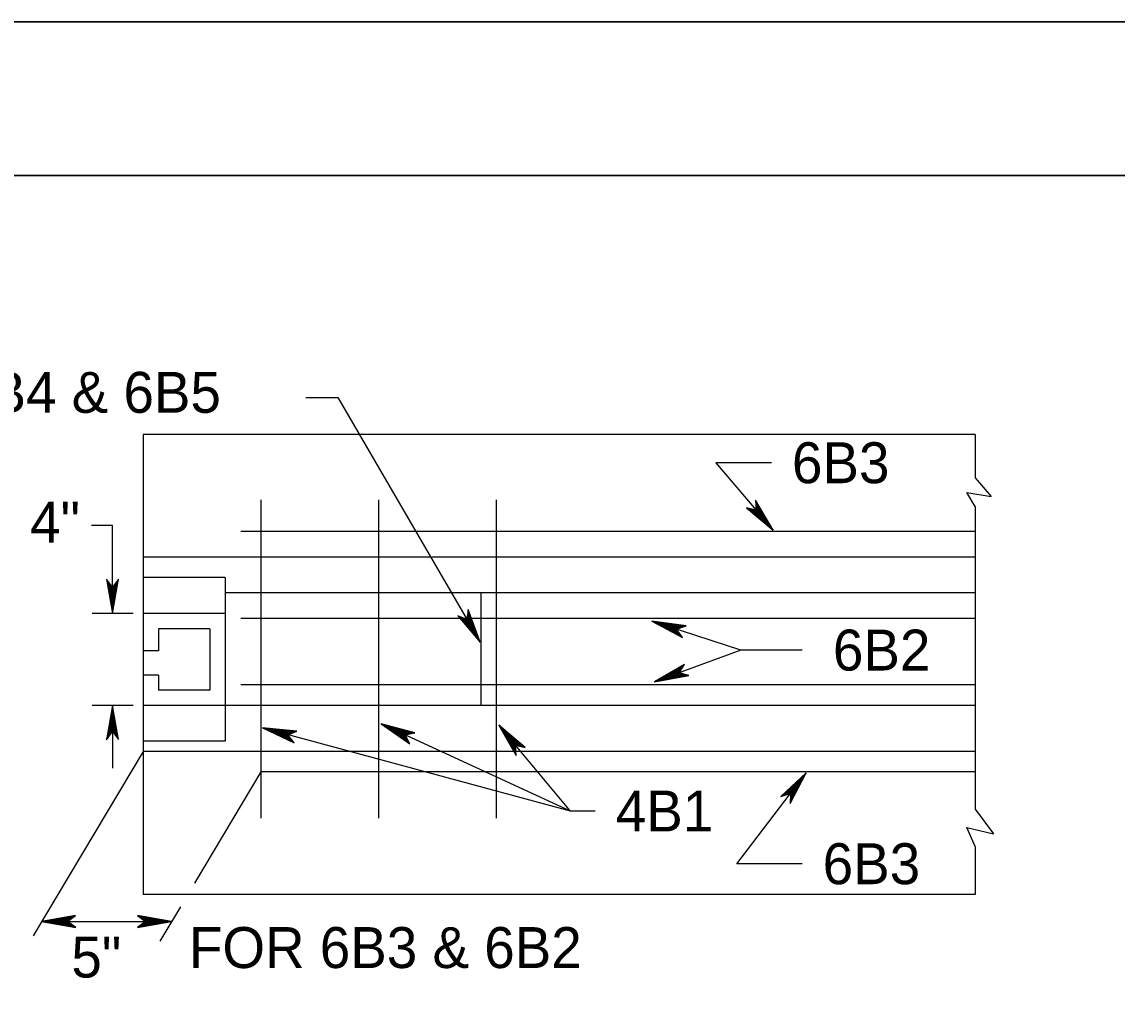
# Model space of a CAD drawing. Extents: x 499883 to 500983, y 499104 to 499764.
# Drawn here: x 500121.3 to 500228.2, y 499669.2 to 499763.6 of the extents above; entities that cross this region are included whole.
import ezdxf

# ---------------------------------------------------------------- set-up
doc = ezdxf.new("R2010")
doc.units = 0
for name, color, linetype in [('1', 7, 'Continuous'), ('24', 7, 'Continuous'), ('41', 7, 'Continuous'), ('5', 7, 'Continuous')]:
    doc.layers.add(name, color=color, linetype=linetype)

msp = doc.modelspace()

# ---------------------------------------------------------------- linework, layer by layer
at = {"layer": '1'}
for p, q in [((500982.94, 499763.64), (499934.77, 499763.64)), ((500979.94, 499748.64), (499989.94, 499748.64))]:
    msp.add_line(p, q, dxfattribs=at)
at = {"layer": '24'}
for points in [[(500194.64, 499714), (500192.91, 499716.93), (500192.98, 499715.94), (500192.03, 499716.16), (500194.64, 499714), (500194.49, 499714.16), (500192.94, 499716.83), (500193.01, 499715.89), (500192.15, 499716.08), (500194.4, 499714.25), (500194.34, 499714.34), (500193, 499716.62), (500193.03, 499715.87), (500192.29, 499716.03), (500194.31, 499714.38), (500194.22, 499714.46), (500193.06, 499716.45), (500193.05, 499715.86), (500192.44, 499715.94), (500194.01, 499714.7), (500193.89, 499714.85), (500193.1, 499716.27), (500193.08, 499715.84), (500192.61, 499715.88), (500193.88, 499714.88), (500193.77, 499715.03), (500193.15, 499716.07), (500193.12, 499715.74), (500192.79, 499715.78), (500193.66, 499715.14), (500193.56, 499715.28), (500193.2, 499715.92), (500193.15, 499715.72), (500192.89, 499715.76), (500193.49, 499715.34), (500193.27, 499715.77), (500193.22, 499715.63), (500192.99, 499715.71), (500193.4, 499715.42), (500193.26, 499715.7), (500193.27, 499715.54), (500193.13, 499715.61), (500193.29, 499715.56), (500193.26, 499715.63)], [(500130.12, 499705.86), (500130.71, 499709.21), (500130.12, 499708.41), (500129.54, 499709.19), (500130.12, 499705.86), (500130.12, 499706.08), (500130.67, 499709.11), (500130.12, 499708.34), (500129.59, 499709.05), (500130.11, 499706.2), (500130.12, 499706.31), (500130.58, 499708.91), (500130.12, 499708.33), (500129.66, 499708.93), (500130.12, 499706.36), (500130.11, 499706.47), (500130.52, 499708.74), (500130.12, 499708.3), (500129.71, 499708.75), (500130.11, 499706.8), (500130.11, 499706.98), (500130.43, 499708.58), (500130.13, 499708.27), (500129.8, 499708.6), (500130.12, 499707.02), (500130.13, 499707.2), (500130.34, 499708.39), (500130.11, 499708.16), (500129.88, 499708.41), (500130.12, 499707.36), (500130.14, 499707.53), (500130.28, 499708.25), (500130.12, 499708.13), (500129.94, 499708.33), (500130.12, 499707.62), (500130.23, 499708.09), (500130.11, 499708.02), (500129.98, 499708.22), (500130.11, 499707.74), (500130.18, 499708.04), (500130.08, 499707.91), (500130.02, 499708.06), (500130.12, 499707.92), (500130.13, 499707.99)], [(500166, 499703.04), (500164.83, 499706.24), (500164.72, 499705.25), (500163.82, 499705.63), (500166, 499703.04), (500165.88, 499703.23), (500164.84, 499706.13), (500164.74, 499705.19), (500163.93, 499705.54), (500165.81, 499703.33), (500165.77, 499703.43), (500164.86, 499705.91), (500164.75, 499705.17), (500164.06, 499705.46), (500165.74, 499703.48), (500165.67, 499703.57), (500164.89, 499705.74), (500164.77, 499705.16), (500164.19, 499705.34), (500165.51, 499703.85), (500165.42, 499704.01), (500164.9, 499705.55), (500164.8, 499705.13), (500164.34, 499705.25), (500165.41, 499704.05), (500165.33, 499704.21), (500164.91, 499705.34), (500164.82, 499705.03), (500164.5, 499705.13), (500165.24, 499704.34), (500165.17, 499704.5), (500164.93, 499705.19), (500164.85, 499705.01), (500164.6, 499705.08), (500165.11, 499704.57), (500164.97, 499705.03), (500164.9, 499704.9), (500164.68, 499705.02), (500165.04, 499704.66), (500164.95, 499704.96), (500164.93, 499704.8), (500164.8, 499704.9), (500164.96, 499704.82), (500164.93, 499704.89)], [(500182.78, 499705.11), (500185.78, 499703.51), (500185.2, 499704.32), (500186.13, 499704.63), (500182.78, 499705.11), (500182.99, 499705.04), (500185.71, 499703.58), (500185.15, 499704.34), (500185.99, 499704.63), (500183.11, 499705.02), (500183.21, 499704.97), (500185.54, 499703.72), (500185.13, 499704.35), (500185.84, 499704.59), (500183.26, 499704.95), (500183.37, 499704.93), (500185.4, 499703.84), (500185.11, 499704.35), (500185.66, 499704.6), (500183.68, 499704.83), (500183.86, 499704.77), (500185.27, 499703.97), (500185.07, 499704.35), (500185.49, 499704.56), (500183.89, 499704.75), (500184.05, 499704.68), (500185.13, 499704.12), (500184.98, 499704.41), (500185.29, 499704.55), (500184.21, 499704.64), (500184.37, 499704.57), (500185.01, 499704.22), (500184.94, 499704.41), (500185.19, 499704.52), (500184.46, 499704.56), (500184.87, 499704.31), (500184.84, 499704.45), (500185.08, 499704.51), (500184.57, 499704.54), (500184.84, 499704.37), (500184.75, 499704.51), (500184.91, 499704.52), (500184.74, 499704.48), (500184.81, 499704.44)], [(500183.04, 499699.18), (500186.39, 499699.78), (500185.43, 499700.06), (500185.97, 499700.87), (500183.04, 499699.18), (500183.24, 499699.26), (500186.28, 499699.79), (500185.37, 499700.04), (500185.85, 499700.78), (500183.35, 499699.31), (500183.46, 499699.34), (500186.06, 499699.8), (500185.35, 499700.04), (500185.76, 499700.67), (500183.51, 499699.35), (500183.61, 499699.41), (500185.88, 499699.8), (500185.33, 499700.02), (500185.62, 499700.56), (500183.91, 499699.52), (500184.09, 499699.58), (500185.7, 499699.83), (500185.3, 499700), (500185.5, 499700.43), (500184.13, 499699.58), (500184.3, 499699.63), (500185.49, 499699.85), (500185.2, 499699.99), (500185.35, 499700.29), (500184.45, 499699.7), (500184.62, 499699.74), (500185.34, 499699.86), (500185.17, 499699.97), (500185.29, 499700.2), (500184.69, 499699.79), (500185.17, 499699.84), (500185.06, 499699.94), (500185.21, 499700.13), (500184.8, 499699.84), (500185.11, 499699.88), (500184.96, 499699.93), (500185.07, 499700.03), (500184.97, 499699.9), (500185.05, 499699.91)], [(500130.12, 499696.86), (500129.53, 499693.51), (500130.12, 499694.31), (500130.71, 499693.53), (500130.12, 499696.86), (500130.13, 499696.64), (500129.57, 499693.61), (500130.13, 499694.38), (500130.66, 499693.66), (500130.14, 499696.52), (500130.12, 499696.41), (500129.66, 499693.81), (500130.13, 499694.39), (500130.58, 499693.79), (500130.12, 499696.36), (500130.14, 499696.25), (500129.73, 499693.97), (500130.12, 499694.42), (500130.53, 499693.97), (500130.14, 499695.92), (500130.14, 499695.73), (500129.81, 499694.14), (500130.11, 499694.45), (500130.45, 499694.12), (500130.12, 499695.7), (500130.11, 499695.52), (500129.91, 499694.32), (500130.14, 499694.55), (500130.37, 499694.31), (500130.12, 499695.36), (500130.11, 499695.19), (500129.97, 499694.47), (500130.13, 499694.59), (500130.31, 499694.39), (500130.12, 499695.1), (500130.01, 499694.63), (500130.14, 499694.7), (500130.27, 499694.49), (500130.14, 499694.98), (500130.06, 499694.68), (500130.16, 499694.8), (500130.22, 499694.66), (500130.13, 499694.8), (500130.11, 499694.73)], [(500144.76, 499694.67), (500147.84, 499693.22), (500147.23, 499694), (500148.13, 499694.36), (500144.76, 499694.67), (500144.98, 499694.62), (500147.76, 499693.29), (500147.17, 499694.03), (500147.99, 499694.35), (500145.1, 499694.6), (500145.2, 499694.55), (500147.59, 499693.43), (500147.15, 499694.03), (500147.85, 499694.31), (500145.25, 499694.54), (500145.36, 499694.52), (500147.45, 499693.54), (500147.13, 499694.03), (500147.67, 499694.31), (500145.68, 499694.44), (500145.86, 499694.39), (500147.31, 499693.66), (500147.09, 499694.03), (500147.5, 499694.27), (500145.89, 499694.37), (500146.06, 499694.31), (500147.16, 499693.8), (500147, 499694.08), (500147.3, 499694.24), (500146.22, 499694.28), (500146.38, 499694.22), (500147.03, 499693.9), (500146.96, 499694.08), (500147.2, 499694.2), (500146.47, 499694.21), (500146.89, 499693.98), (500146.86, 499694.12), (500147.09, 499694.19), (500146.58, 499694.2), (500146.86, 499694.04), (500146.76, 499694.17), (500146.92, 499694.19), (500146.75, 499694.14), (500146.82, 499694.1)], [(500156.36, 499695.06), (500159.16, 499693.12), (500158.68, 499693.99), (500159.63, 499694.19), (500156.36, 499695.06), (500156.57, 499694.97), (500159.09, 499693.2), (500158.62, 499694.02), (500159.49, 499694.21), (500156.68, 499694.93), (500156.77, 499694.87), (500158.94, 499693.36), (500158.61, 499694.03), (500159.34, 499694.19), (500156.82, 499694.84), (500156.93, 499694.81), (500158.82, 499693.49), (500158.58, 499694.03), (500159.16, 499694.21), (500157.22, 499694.68), (500157.39, 499694.6), (500158.7, 499693.64), (500158.55, 499694.04), (500158.99, 499694.2), (500157.42, 499694.57), (500157.58, 499694.49), (500158.58, 499693.8), (500158.46, 499694.11), (500158.79, 499694.21), (500157.73, 499694.43), (500157.88, 499694.34), (500158.47, 499693.91), (500158.43, 499694.11), (500158.68, 499694.19), (500157.96, 499694.32), (500158.34, 499694.02), (500158.33, 499694.17), (500158.57, 499694.2), (500158.08, 499694.28), (500158.32, 499694.09), (500158.25, 499694.23), (500158.41, 499694.22), (500158.24, 499694.2), (500158.3, 499694.15)], [(500167.83, 499694.93), (500169.52, 499691.98), (500169.46, 499692.97), (500170.41, 499692.74), (500167.83, 499694.93), (500167.98, 499694.76), (500169.5, 499692.08), (500169.43, 499693.02), (500170.29, 499692.82), (500168.06, 499694.67), (500168.12, 499694.58), (500169.43, 499692.29), (500169.42, 499693.04), (500170.15, 499692.87), (500168.15, 499694.54), (500168.24, 499694.46), (500169.38, 499692.46), (500169.4, 499693.05), (500170, 499692.96), (500168.45, 499694.22), (500168.57, 499694.07), (500169.34, 499692.64), (500169.37, 499693.07), (500169.84, 499693.03), (500168.58, 499694.03), (500168.68, 499693.89), (500169.29, 499692.84), (500169.32, 499693.17), (500169.66, 499693.12), (500168.8, 499693.77), (500168.89, 499693.63), (500169.25, 499692.99), (500169.29, 499693.19), (500169.56, 499693.15), (500168.96, 499693.57), (500169.17, 499693.14), (500169.23, 499693.28), (500169.46, 499693.2), (500169.05, 499693.49), (500169.19, 499693.21), (500169.18, 499693.37), (500169.32, 499693.3), (500169.16, 499693.35), (500169.19, 499693.28)], [(500197.86, 499690.29), (500195.36, 499687.98), (500196.31, 499688.26), (500196.3, 499687.28), (500197.86, 499690.29), (500197.73, 499690.11), (500195.45, 499688.03), (500196.36, 499688.3), (500196.35, 499687.42), (500197.66, 499690.01), (500197.58, 499689.93), (500195.64, 499688.14), (500196.37, 499688.32), (500196.36, 499687.57), (500197.55, 499689.89), (500197.5, 499689.79), (500195.79, 499688.23), (500196.37, 499688.34), (500196.43, 499687.74), (500197.3, 499689.53), (500197.19, 499689.38), (500195.96, 499688.31), (500196.39, 499688.38), (500196.45, 499687.91), (500197.15, 499689.36), (500197.04, 499689.23), (500196.15, 499688.4), (500196.47, 499688.44), (500196.5, 499688.1), (500196.94, 499689.09), (500196.83, 499688.97), (500196.28, 499688.48), (500196.48, 499688.47), (500196.51, 499688.21), (500196.79, 499688.89), (500196.42, 499688.58), (500196.56, 499688.56), (500196.54, 499688.32), (500196.73, 499688.78), (500196.48, 499688.58), (500196.64, 499688.63), (500196.6, 499688.47), (500196.62, 499688.65), (500196.56, 499688.59)], [(500123.19, 499675.75), (500126.52, 499675.16), (500125.72, 499675.75), (500126.5, 499676.33), (500123.19, 499675.75), (500123.41, 499675.76), (500126.42, 499675.21), (500125.66, 499675.76), (500126.36, 499676.28), (500123.53, 499675.77), (500123.64, 499675.75), (500126.22, 499675.29), (500125.64, 499675.76), (500126.24, 499676.21), (500123.69, 499675.75), (500123.8, 499675.77), (500126.06, 499675.36), (500125.62, 499675.75), (500126.07, 499676.16), (500124.13, 499675.77), (500124.31, 499675.77), (500125.89, 499675.45), (500125.58, 499675.74), (500125.91, 499676.07), (500124.35, 499675.75), (500124.52, 499675.74), (500125.71, 499675.54), (500125.48, 499675.77), (500125.73, 499676), (500124.69, 499675.75), (500124.85, 499675.74), (500125.57, 499675.6), (500125.45, 499675.76), (500125.64, 499675.94), (500124.94, 499675.75), (500125.41, 499675.64), (500125.34, 499675.77), (500125.54, 499675.9), (500125.06, 499675.77), (500125.36, 499675.69), (500125.23, 499675.79), (500125.38, 499675.85), (500125.24, 499675.76), (500125.31, 499675.74)], [(500135.88, 499675.75), (500132.55, 499676.34), (500133.35, 499675.75), (500132.57, 499675.17), (500135.88, 499675.75), (500135.66, 499675.75), (500132.65, 499676.3), (500133.41, 499675.74), (500132.71, 499675.22), (500135.54, 499675.74), (500135.43, 499675.75), (500132.85, 499676.21), (500133.43, 499675.75), (500132.83, 499675.29), (500135.38, 499675.75), (500135.27, 499675.74), (500133.01, 499676.14), (500133.45, 499675.75), (500133, 499675.35), (500134.95, 499675.74), (500134.76, 499675.74), (500133.18, 499676.06), (500133.49, 499675.76), (500133.16, 499675.43), (500134.72, 499675.75), (500134.55, 499675.76), (500133.36, 499675.97), (500133.59, 499675.74), (500133.34, 499675.51), (500134.38, 499675.75), (500134.22, 499675.77), (500133.5, 499675.91), (500133.62, 499675.74), (500133.43, 499675.57), (500134.13, 499675.75), (500133.66, 499675.86), (500133.73, 499675.74), (500133.53, 499675.61), (500134.01, 499675.74), (500133.71, 499675.81), (500133.84, 499675.71), (500133.69, 499675.65), (500133.83, 499675.74), (500133.76, 499675.76)]]:
    msp.add_lwpolyline(points, dxfattribs=at)
at = {"layer": '41'}
for points in [[(499934.77, 499763.64), (500982.94, 499763.64), (500982.94, 499103.64), (499934.77, 499103.64)], [(499989.94, 499748.64), (500979.94, 499748.64), (500979.94, 499118.64), (499989.94, 499118.64)]]:
    msp.add_lwpolyline(points, close=True, dxfattribs=at)
at = {"layer": '5'}
for p, q in [((500214.34, 499723.34), (500133.12, 499723.34)), ((500133.12, 499723.34), (500133.12, 499678.38)), ((500214.34, 499723.34), (500214.34, 499719.11)), ((500214.34, 499719.11), (500215.9, 499717.26)), ((500144.61, 499716.95), (500144.61, 499685.86)), ((500156.1, 499716.95), (500156.1, 499685.86)), ((500167.59, 499716.95), (500167.59, 499685.86)), ((500214.34, 499716.29), (500213.53, 499717.66)), ((500213.53, 499717.66), (500215.9, 499717.26)), ((500214.34, 499716.29), (500214.34, 499686.73)), ((500214.34, 499713.85), (500142.65, 499713.85)), ((500214.34, 499711.35), (500133.12, 499711.35)), ((500141.11, 499709.35), (500133.12, 499709.35)), ((500141.11, 499709.35), (500141.11, 499696.86)), ((500214.34, 499707.85), (500141.11, 499707.85)), ((500166.09, 499707.85), (500166.09, 499696.86)), ((500132.14, 499705.86), (500128.12, 499705.86)), ((500141.11, 499705.86), (500133.12, 499705.86)), ((500214.34, 499705.36), (500142.65, 499705.36)), ((500191.47, 499702.27), (500182.78, 499705.11)), ((500139.61, 499704.36), (500134.62, 499704.36)), ((500134.62, 499704.36), (500134.62, 499702.21)), ((500139.61, 499704.36), (500139.61, 499698.36)), ((500134.62, 499702.21), (500133.12, 499702.21)), ((500191.47, 499702.27), (500183.04, 499699.18)), ((500197.46, 499702.27), (500191.47, 499702.27)), ((500134.62, 499699.82), (500133.12, 499699.82)), ((500134.62, 499699.82), (500134.62, 499698.36)), ((500214.34, 499698.86), (500142.65, 499698.86)), ((500139.61, 499698.36), (500134.62, 499698.36)), ((500132.14, 499696.86), (500128.12, 499696.86)), ((500130.12, 499696.86), (500130.12, 499690.73)), ((500141.11, 499696.86), (500133.12, 499696.86)), ((500214.34, 499696.86), (500141.11, 499696.86)), ((500141.11, 499696.86), (500141.11, 499693.36)), ((500174.82, 499686.55), (500144.76, 499694.67)), ((500174.82, 499686.55), (500167.83, 499694.93)), ((500141.11, 499693.36), (500133.12, 499693.36)), ((500133.12, 499692.37), (500122.36, 499674.37)), ((500214.34, 499692.37), (500133.12, 499692.37)), ((500144.61, 499690.37), (500138.11, 499679.49)), ((500214.34, 499690.37), (500144.61, 499690.37)), ((500214.34, 499686.73), (500216.14, 499684.31)), ((500214.34, 499683.07), (500213.53, 499684.95)), ((500213.53, 499684.95), (500216.14, 499684.31)), ((500214.34, 499683.07), (500214.34, 499678.38)), ((500214.34, 499678.38), (500133.12, 499678.38)), ((500136.75, 499677.2), (500134.73, 499673.83)), ((500123.19, 499675.75), (500135.88, 499675.75))]:
    msp.add_line(p, q, dxfattribs=at)
for points in [[(500149, 499726.96), (500152.12, 499726.96), (500166, 499703.04)], [(500194.46, 499720.57), (500189.02, 499720.57), (500194.64, 499714)], [(500130.12, 499705.86), (500130.12, 499714.44), (500128.07, 499714.44)], [(500177.26, 499686.55), (500174.82, 499686.55), (500156.36, 499695.06)], [(500197.46, 499681.4), (500191.09, 499681.4), (500197.86, 499690.29)]]:
    msp.add_lwpolyline(points, dxfattribs=at)

# ---------------------------------------------------------------- texts
for s, p in [('6B4 & 6B5', (500115.13, 499725.45)), ('6B3', (500196.46, 499718.57)), ('4"', (500122.07, 499712.78)), ('6B2', (500200.46, 499700.27)), ('4B1', (500179.26, 499684.55)), ('6B3', (500199.46, 499679.4)), ('FOR 6B3 & 6B2 ', (500137.58, 499671.21)), ('5"', (500126.1, 499670.28))]:
    msp.add_text(s, height=4, dxfattribs=at).set_placement(p)

doc.saveas('drawing.dxf')
